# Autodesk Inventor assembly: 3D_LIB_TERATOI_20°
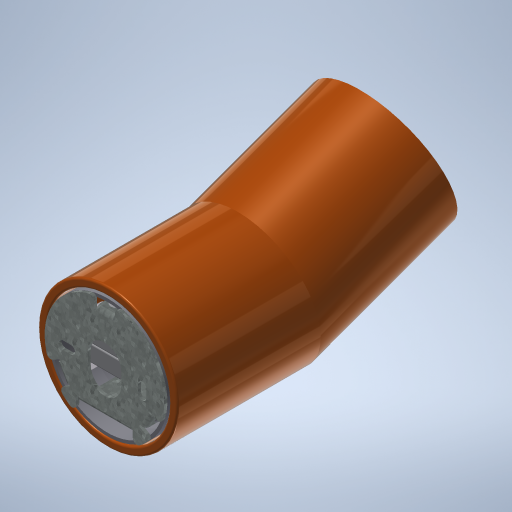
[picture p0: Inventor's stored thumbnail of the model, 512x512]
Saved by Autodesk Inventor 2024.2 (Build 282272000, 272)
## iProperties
Manager: DarkStudio
Company: DARK
Created: 2022-11
Part Number: 3D_LIB_TERATOI_20°
Document SubType Name: Assembly
Designer: DarkStudio
Engineer: DarkStudio
Project: 444 - TERATOI
Description: TERATOI - 20°
Author: DarkStudio
Revision Number: V2
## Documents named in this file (19)
- C:\Users\Stage\Desktop\Stage Karsten\armatures\444 - TERATOI\V4\444_KARSTEN\3D_LIB_TERATOI_20°.iam
- C:\Users\Stage\Desktop\Stage Karsten\armatures\444 - TERATOI\V4\444-002.ipt
- C:\Users\Stage\Desktop\Stage Karsten\armatures\444 - TERATOI\V4\Veerring DIN 6798 M4.ipt
- C:\Users\Stage\Desktop\Stage Karsten\armatures\444 - TERATOI\V4\GU10 - SPOT.ipt
- C:\Users\Stage\Desktop\Stage Karsten\armatures\444 - TERATOI\V4\GU10 BJB 25.819.ipt
- C:\Users\Stage\Desktop\Stage Karsten\armatures\444 - TERATOI\V4\444-004.ipt
- C:\Users\Stage\Desktop\Stage Karsten\armatures\444 - TERATOI\V4\444-006.ipt
- C:\Users\Stage\Desktop\Stage Karsten\armatures\444 - TERATOI\V4\Trompetnippel platte kanten M10 x 1 x 10.ipt
- C:\Users\Stage\Desktop\Stage Karsten\armatures\444 - TERATOI\V4\fiberring 14x10x1mm.ipt
- C:\Users\Stage\Desktop\Stage Karsten\armatures\444 - TERATOI\V4\82297000 -0-000 = 092-018.ipt
- C:\Users\Stage\Desktop\Stage Karsten\armatures\444 - TERATOI\V4\444-009.ipt
- C:\Users\Stage\Desktop\Stage Karsten\armatures\444 - TERATOI\V4\poprivet 2.9 x 5.ipt
- C:\Users\Stage\Desktop\Stage Karsten\armatures\444 - TERATOI\V4\DIN 7985 M4  x 6.ipt
- C:\Users\Stage\Desktop\Stage Karsten\armatures\444 - TERATOI\V4\444-010.ipt
- C:\Users\Stage\Desktop\Stage Karsten\armatures\444 - TERATOI\V4\DIN 7985 M3 x 4.ipt
- C:\Users\Stage\Desktop\Stage Karsten\armatures\444 - TERATOI\V4\Bendler_Platte_Din6879a.ipt
- C:\Users\Stage\Desktop\TUUR\2D en 3D\TERATOI\444 - TERATOI\V4\DIN 7985 M3 x 8.ipt
- C:\Users\Stage\Desktop\Stage Karsten\armatures\444 - TERATOI\V4\444-011.ipt
- C:\Users\Stage\Desktop\Stage Karsten\armatures\444 - TERATOI\V4\WAGO 221-413_2_14 splicing connector 3P.ipt
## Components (24 placed, 18 different names)
1. 444-002:1 — Mate:53, Flush:4, Mate:64, Mate:65, Flush:77, Mate:76
2. 444-006:1 — Mate:49, Mate:50, Mate:74, Flush:77, Mate:76
3. 444-004:1
4. GU10 BJB 25.819:1 — Mate:84
5. GU10 - SPOT:1 — Mate:74
6. DIN 7985 M3 x 12:2
7. DIN 7985 M3 x 12:1
8. Trompetnippel platte kanten M10 x 1 x 10:1 — Mate:45, Mate:47, Mate:66, Mate:69, Angle:2, Mate:80
9. 444-011:1 — Mate:84
10. fiberring 14x10x1mm:1 — Mate:45, Mate:46
11. 82297000 -0-000 = 092-018:1 — Mate:46, Mate:47, Mate:71
12. DIN 7985 M4  x 6:1 — Mate:59, Mate:60
13. Veerring DIN 6798 M4:2 — Mate:60, Mate:61
14. 444-010:1
15. DIN 7985 M3 x 4:1 — Mate:65, Flush:5
16. Bendler_Platte_Din6879a:1 — Mate:69, Mate:71
17. WAGO 221-413_2_14 splicing connector 3P:1 — Mate:86, Mate:87
18. WAGO 221-413_2_14 splicing connector 3P:2
19. 444-009:1 — Mate:55, Mate:56, Angle:1
20. poprivet 2.9 x 5:1 — Mate:54, Mate:56, Mate:57
21. 444-009:2
22. poprivet 2.9 x 5:2
23. 444-009:3
24. poprivet 2.9 x 5:3
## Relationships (29: Mate 24, Flush 3, Angle 2)
- Mate:45: Trompetnippel platte kanten M10 x 1 x 10:1 ↔ fiberring 14x10x1mm:1
- Mate:46: fiberring 14x10x1mm:1 ↔ 82297000 -0-000 = 092-018:1
- Mate:47: Trompetnippel platte kanten M10 x 1 x 10:1 ↔ 82297000 -0-000 = 092-018:1
- Mate:49: 444-006:1
- Mate:50: 444-006:1
- Mate:53: 444-002:1
- Mate:54: poprivet 2.9 x 5:1
- Mate:55: 444-009:1
- Mate:56: 444-009:1 ↔ poprivet 2.9 x 5:1
- Angle:1: 444-009:1
- Mate:57: poprivet 2.9 x 5:1
- Mate:59: DIN 7985 M4  x 6:1
- Mate:60: DIN 7985 M4  x 6:1 ↔ Veerring DIN 6798 M4:2
- Mate:61: Veerring DIN 6798 M4:2
- Flush:4: 444-002:1
- Mate:64: 444-002:1
- Mate:65: 444-002:1 ↔ DIN 7985 M3 x 4:1
- Flush:5: DIN 7985 M3 x 4:1
- Mate:66: Trompetnippel platte kanten M10 x 1 x 10:1
- Mate:69: Trompetnippel platte kanten M10 x 1 x 10:1 ↔ Bendler_Platte_Din6879a:1
- Mate:71: 82297000 -0-000 = 092-018:1 ↔ Bendler_Platte_Din6879a:1
- Mate:74: 444-006:1 ↔ GU10 - SPOT:1
- Flush:77: 444-002:1 ↔ 444-006:1
- Mate:76: 444-002:1 ↔ 444-006:1
- Angle:2: Trompetnippel platte kanten M10 x 1 x 10:1
- Mate:80: Trompetnippel platte kanten M10 x 1 x 10:1
- Mate:84: GU10 BJB 25.819:1 ↔ 444-011:1
- Mate:86: WAGO 221-413_2_14 splicing connector 3P:1
- Mate:87: WAGO 221-413_2_14 splicing connector 3P:1
## Named parameters: d81_d54 = 0, d85_d65 = 0, d86_d63 = 0, d121_d68 = 0, d122_d69 = 0, d123_d70 = 0
